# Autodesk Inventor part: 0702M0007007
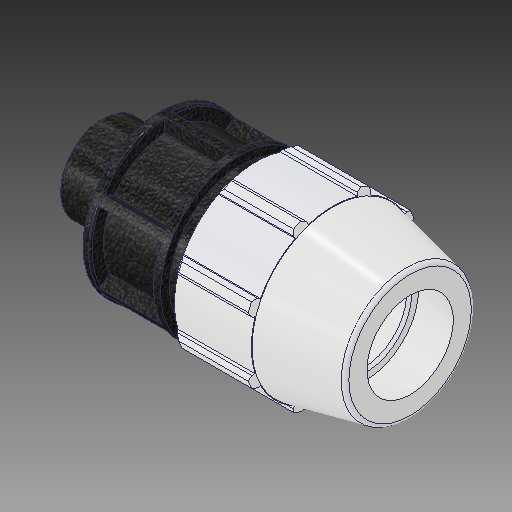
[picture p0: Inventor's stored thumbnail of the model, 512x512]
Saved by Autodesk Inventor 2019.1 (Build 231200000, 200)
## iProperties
Created: 2017-02
Part Number: 0702M0007007
Material: PVC-Piping
Description: PLASSON MALE ADAPTOR 3/4'' - 3/4''M
Document SubType Name: Modeling
Designer: KIM
Mass: 92.6774 g
Surface Area: 199.44 cm^2
Volume: 66.1981 cm^3
Density: 1.4 g/cm^3
Appearance: PTFE
Author: KIM
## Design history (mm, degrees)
derived "0702M0.ipt"
feature "Solid1::0702M0.ipt"
tag "TaggingFeature1"
body "Solid1"
other parameters: "d2" = 26.6, "d4" = 13.57086, "d5" = 23.749, "d7" = 54.102, "d8" = 40.5765, "d9" = 13.57086, "d11" = 2.71417, "d12" = 43.2816, "d13" = 120 deg, "d14" = 39.9, "d15" = 12 deg, "d16" = 48.6918, "d18" = 1.33, "d19" = 35 deg, "d20" = 17.5 deg, "d21" = 50.31486, "d23" = 0, "d25" = 360 deg, "d27" = 1.08204, "d34" = 2.7051, "d36" = 0, "d42" = 23.749, "d43" = 1.62306, "d46" = 0.798, "d49" = 71.882, "d51" = 94.996, "d52" = 18.034, "d53" = 0.532, "d55" = 360 deg, "d57" = 26.441, "d58" = 18.5087, "d59" = 18.9992, "d_" = 26.6, "E_" = 54.102, "H_" = 94.996, "l_" = 71.882, "l_2" = 18.034, "G_" = 26.441
